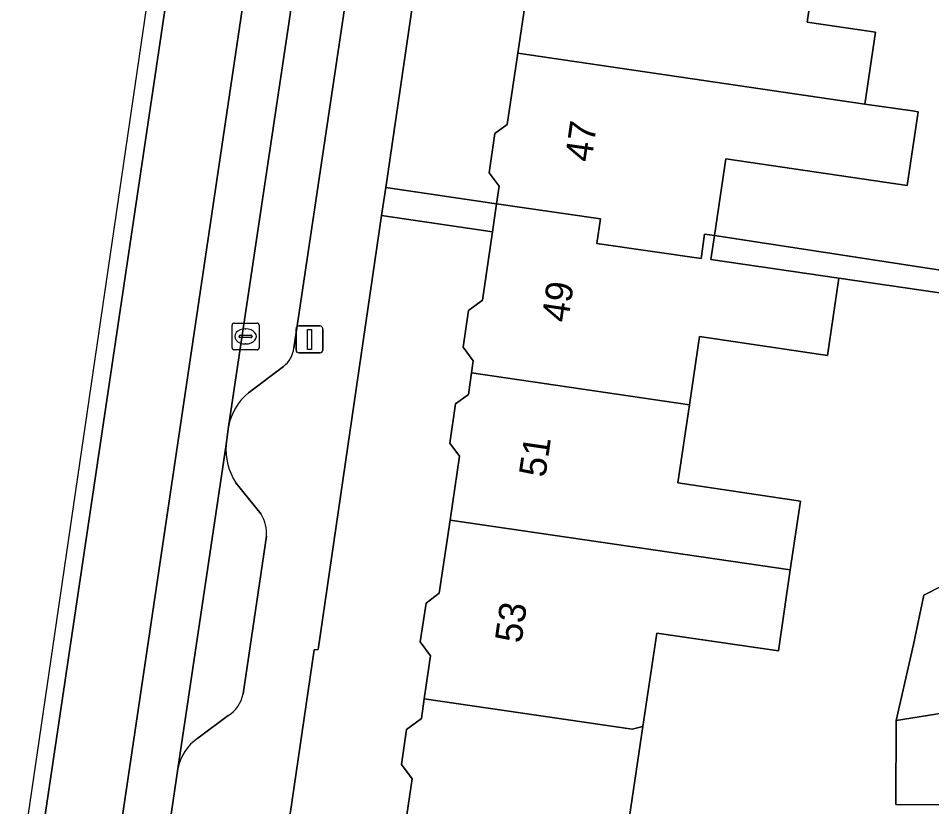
# Model space of a CAD drawing. Extents: x 162250 to 162661, y 380743 to 381606.
# Drawn here: x 162321.06 to 162355.04, y 381382.1 to 381411.43 of the extents above; entities that cross this region are included whole.
import ezdxf

# ---------------------------------------------------------------- set-up
doc = ezdxf.new("R2010")
doc.units = 0
for name, color, linetype in [('IMGEO_Erf', 7, 'Continuous'), ('IMGEO_Kolk', 7, 'Continuous'), ('IMGEO_Lichtmast', 7, 'Continuous'), ('IMGEO_Pand', 7, 'Continuous'), ('IMGEO_Pand_nummerreeks', 7, 'Continuous'), ('IMGEO_Parkeervlak_open', 7, 'Continuous'), ('IMGEO_Rijbaan_lokaal_gesloten', 7, 'Continuous'), ('IMGEO_Rijbaan_lokaal_open', 7, 'Continuous'), ('IMGEO_Voetpad_open', 7, 'Continuous')]:
    doc.layers.add(name, color=color, linetype=linetype)

msp = doc.modelspace()

# ---------------------------------------------------------------- linework, layer by layer
at = {"layer": 'IMGEO_Erf'}
for points in [[(162338.89, 381433.553), (162334.728, 381405.133), (162338.853, 381404.529), (162338.949, 381405.179), (162338.573, 381405.685), (162338.788, 381407.138), (162339.25, 381407.481), (162339.641, 381410.127), (162340.001, 381412.566)], [(162350.768, 381413.723), (162350.412, 381411.289), (162352.951, 381410.914), (162352.555, 381408.238), (162354.32, 381407.98), (162354.536, 381407.946), (162354.13, 381405.202), (162347.377, 381406.2), (162346.955, 381403.343), (162373.077, 381399.345), (162375.677, 381398.98), (162378.363, 381398.602), (162381.05, 381398.225), (162383.737, 381397.847), (162386.424, 381397.47), (162386.104, 381406.654), (162398.76, 381412.894)], [(162335.056, 381378.696), (162335.711, 381383.129), (162335.309, 381383.67), (162335.501, 381384.968), (162336.054, 381385.378), (162336.163, 381386.115), (162336.399, 381387.712), (162336.013, 381388.232), (162336.226, 381389.674), (162336.72, 381390.041), (162337.122, 381392.761), (162337.473, 381395.14), (162337.112, 381395.626), (162337.327, 381397.082), (162337.801, 381397.434), (162337.919, 381398.234), (162337.986, 381398.684), (162337.606, 381399.195), (162337.808, 381400.561), (162338.323, 381400.943), (162338.699, 381403.489), (162334.576, 381404.093), (162332.211, 381387.945), (162332.068, 381387.938), (162330.281, 381375.735)], [(162360.858, 381400.414), (162351.59, 381401.756), (162351.165, 381398.884), (162346.399, 381399.588), (162346.024, 381397.048), (162345.595, 381394.143), (162350.157, 381393.469), (162349.779, 381390.908), (162349.334, 381387.89), (162344.808, 381388.559), (162344.295, 381385.086), (162343.8, 381381.738)]]:
    msp.add_lwpolyline(points, dxfattribs=at)
msp.add_lwpolyline([(162358.135, 381391.689), (162356.982, 381385.822), (162356.26, 381382.172), (162353.699, 381382.181), (162353.72, 381385.307), (162354.36, 381388.13), (162354.752, 381389.967)], close=True, dxfattribs=at)
at = {"layer": 'IMGEO_Kolk'}
for p, q in [((162329.012, 381399.166), (162329.012, 381400.018)), ((162329.087, 381400.092), (162329.939, 381400.092)), ((162330.013, 381400.018), (162330.013, 381399.166)), ((162329.5, 381399.872), (162329.525, 381399.872)), ((162329.271, 381399.586), (162329.271, 381399.598)), ((162329.709, 381399.549), (162329.311, 381399.549)), ((162329.314, 381399.635), (162329.712, 381399.635)), ((162329.755, 381399.598), (162329.755, 381399.586)), ((162329.939, 381399.092), (162329.087, 381399.092)), ((162329.523, 381399.312), (162329.498, 381399.312))]:
    msp.add_line(p, q, dxfattribs=at)
for points in [[(162329.012, 381399.166), (162329.012, 381400.018)], [(162329.087, 381400.092), (162329.939, 381400.092)], [(162330.013, 381400.018), (162330.013, 381399.166)], [(162329.939, 381399.092), (162329.087, 381399.092)]]:
    msp.add_lwpolyline(points, dxfattribs=at)
for centre, radius, start, end in [((162329.089, 381400.016), 0.0765, 91.552, 178.448), ((162329.089, 381400.016), 0.0765, 91.552, 178.448), ((162329.937, 381400.016), 0.0765, 1.552, 88.448), ((162329.937, 381400.016), 0.0765, 1.552, 88.448), ((162329.311, 381399.595), 0.0403, 85.8775, 175.7526), ((162329.308, 381399.585), 0.0366, 178.938, 274.7102), ((162329.712, 381399.592), 0.043, 264.8664, 352.4533), ((162329.716, 381399.597), 0.0386, 1.7309, 96.639), ((162329.089, 381399.168), 0.0765, 181.552, 268.448), ((162329.089, 381399.168), 0.0765, 181.552, 268.448), ((162329.937, 381399.168), 0.0765, 271.552, 358.448), ((162329.937, 381399.168), 0.0765, 271.552, 358.448)]:
    msp.add_arc(centre, radius, start, end, dxfattribs=at)
for centre, major_axis, ratio, start_param, end_param in [((162329.499, 381399.592), (-0.387, 0.002), 0.722429, 4.712389, 7.853982), ((162329.524, 381399.592), (-0.39, 0.002), 0.717154, 1.570796, 4.712389)]:
    msp.add_ellipse(centre, major_axis=major_axis, ratio=ratio, start_param=start_param, end_param=end_param, dxfattribs=at)
at = {"layer": 'IMGEO_Lichtmast'}
for p, q in [((162331.393, 381399.081), (162331.393, 381399.881)), ((162331.393, 381399.881), (162331.393, 381399.081)), ((162331.493, 381399.981), (162332.283, 381399.981)), ((162332.283, 381399.981), (162331.493, 381399.981)), ((162332.383, 381399.881), (162332.383, 381399.081)), ((162332.383, 381399.081), (162332.383, 381399.881)), ((162332.283, 381398.981), (162331.493, 381398.981)), ((162331.493, 381398.981), (162332.283, 381398.981))]:
    msp.add_line(p, q, dxfattribs=at)
msp.add_lwpolyline([(162331.813, 381399.856), (162331.963, 381399.856), (162331.963, 381399.106), (162331.813, 381399.106), (162331.813, 381399.856)], dxfattribs=at)
for centre, start, end in [((162331.493, 381399.881), 90, 180), ((162331.493, 381399.881), 90, 180), ((162332.283, 381399.881), 0, 90), ((162332.283, 381399.881), 360, 90), ((162331.493, 381399.081), 180, 270), ((162331.493, 381399.081), 180, 270), ((162332.283, 381399.081), 270, 0), ((162332.283, 381399.081), 270, 0)]:
    msp.add_arc(centre, 0.1, start, end, dxfattribs=at)
at = {"layer": 'IMGEO_Pand'}
for points in [[(162350.768, 381413.723), (162350.805, 381413.95), (162348.599, 381414.289), (162348.734, 381415.534), (162340.6, 381416.724), (162340.321, 381414.841), (162339.852, 381414.492), (162339.639, 381413.054), (162340.001, 381412.566), (162339.641, 381410.127), (162352.555, 381408.238), (162352.951, 381410.914), (162350.412, 381411.289)], [(162347.377, 381406.2), (162354.13, 381405.202), (162354.536, 381407.946), (162354.32, 381407.98), (162352.555, 381408.238), (162339.641, 381410.127), (162339.25, 381407.481), (162338.788, 381407.138), (162338.573, 381405.685), (162338.949, 381405.179), (162338.853, 381404.529), (162342.712, 381403.964), (162342.579, 381403.056), (162346.457, 381402.489), (162346.59, 381403.397), (162346.955, 381403.343)], [(162351.59, 381401.756), (162346.825, 381402.46), (162346.955, 381403.343), (162346.59, 381403.397), (162346.457, 381402.489), (162342.579, 381403.056), (162342.712, 381403.964), (162338.853, 381404.529), (162338.699, 381403.489), (162338.323, 381400.943), (162337.808, 381400.561), (162337.606, 381399.195), (162337.986, 381398.684), (162337.919, 381398.234), (162346.024, 381397.048), (162346.399, 381399.588), (162351.165, 381398.884)], [(162346.024, 381397.048), (162337.919, 381398.234), (162337.801, 381397.434), (162337.327, 381397.082), (162337.112, 381395.626), (162337.473, 381395.14), (162337.122, 381392.761), (162349.779, 381390.908), (162350.157, 381393.469), (162345.595, 381394.143)], [(162349.779, 381390.908), (162337.122, 381392.761), (162336.72, 381390.041), (162336.226, 381389.674), (162336.013, 381388.232), (162336.399, 381387.712), (162336.163, 381386.115), (162343.896, 381384.983), (162344.295, 381385.086), (162344.808, 381388.559), (162349.334, 381387.89)], [(162353.72, 381385.307), (162356.982, 381385.822), (162358.135, 381391.689), (162354.752, 381389.967), (162354.36, 381388.13)], [(162344.295, 381385.086), (162343.896, 381384.983), (162336.163, 381386.115), (162336.054, 381385.378), (162335.501, 381384.968), (162335.309, 381383.67), (162335.711, 381383.129), (162335.056, 381378.696), (162336.071, 381377.329), (162344.528, 381376.079), (162344.66, 381376.975), (162348.321, 381376.436), (162348.988, 381380.972), (162343.8, 381381.738)], [(162356.982, 381385.822), (162353.72, 381385.307), (162353.699, 381382.181), (162356.26, 381382.172)]]:
    msp.add_lwpolyline(points, close=True, dxfattribs=at)
at = {"layer": 'IMGEO_Parkeervlak_open'}
for points in [[(162335.68, 381441.768), (162328.878, 381396.23)], [(162331.307, 381399.157), (162336.334, 381432.816)], [(162329.621, 381397.5), (162330.928, 381398.477)], [(162328.79, 381395.572), (162326.988, 381383.502)], [(162330.094, 381392.976), (162329.156, 381394.151)], [(162329.418, 381386.291), (162330.287, 381392.156)], [(162327.738, 381384.647), (162328.862, 381385.485)]]:
    msp.add_lwpolyline(points, dxfattribs=at)
for centre, radius, start, end in [((162330.281, 381399.283), 1.034, 308.7422, 352.9913), ((162331.004, 381395.839), 2.161, 129.7702, 169.5711), ((162330.948, 381395.37), 2.168, 174.6603, 214.2266), ((162329.014, 381392.289), 1.279, 354.0243, 32.4645), ((162328.202, 381386.535), 1.241, 302.1584, 348.6438), ((162328.76, 381383.159), 1.805, 124.489, 169.0597)]:
    msp.add_arc(centre, radius, start, end, dxfattribs=at)
at = {"layer": 'IMGEO_Rijbaan_lokaal_gesloten'}
for points in [[(162321.057, 381379.295), (162321.057, 381379.295), (162321.673, 381379.215), (162345.986, 381542.729), (162344.886, 381542.888), (162337.941, 381494.596)], [(162342.842, 381489.774), (162343.13, 381491.968), (162349.998, 381538.218), (162350.562, 381542.047), (162348.846, 381542.303), (162344.03, 381510.414), (162324.497, 381378.848), (162326.277, 381378.617), (162326.988, 381383.502), (162328.79, 381395.572), (162328.878, 381396.23), (162335.68, 381441.768), (162335.989, 381444.267)]]:
    msp.add_lwpolyline(points, close=True, dxfattribs=at)
at = {"layer": 'IMGEO_Rijbaan_lokaal_open'}
msp.add_lwpolyline([(162321.673, 381379.215), (162324.497, 381378.848), (162344.03, 381510.414), (162348.846, 381542.303), (162345.986, 381542.729)], close=True, dxfattribs=at)
at = {"layer": 'IMGEO_Voetpad_open'}
for points in [[(162331.099, 381370.386), (162331.101, 381374.491), (162330.281, 381375.735), (162332.068, 381387.938), (162332.211, 381387.945), (162334.576, 381404.093), (162334.728, 381405.133), (162338.89, 381433.553), (162339.214, 381435.764), (162339.996, 381441.104), (162343.449, 381463.697), (162345.762, 381479.541), (162345.951, 381480.835), (162350.479, 381511.856), (162350.791, 381513.94), (162350.929, 381514.861), (162358.055, 381562.41), (162359.403, 381573.306), (162359.448, 381578.123), (162362.669, 381579.584), (162363.286, 381580.314), (162361.6, 381584.081), (162363.369, 381585.251), (162370.283, 381588.375)], [(162337.12, 381438.08), (162336.991, 381437.217), (162336.334, 381432.816), (162331.307, 381399.157)], [(162330.928, 381398.477), (162329.621, 381397.5)], [(162328.878, 381396.23), (162328.79, 381395.572)], [(162329.156, 381394.151), (162330.094, 381392.976)], [(162330.287, 381392.156), (162329.418, 381386.291)], [(162328.862, 381385.485), (162327.738, 381384.647)], [(162326.988, 381383.502), (162326.277, 381378.617), (162326.057, 381376.827)]]:
    msp.add_lwpolyline(points, dxfattribs=at)
for points in [[(162338.853, 381404.529), (162334.728, 381405.133), (162334.576, 381404.093), (162338.699, 381403.489)], [(162346.955, 381403.343), (162346.825, 381402.46), (162351.59, 381401.756), (162360.858, 381400.414), (162360.87, 381400.499), (162368.468, 381399.398), (162368.328, 381398.244), (162365.555, 381396.74), (162362.518, 381395.093), (162362.518, 381394.554), (162362.518, 381394.226), (162362.518, 381394.063), (162366.054, 381395.832), (162373.077, 381399.345)]]:
    msp.add_lwpolyline(points, close=True, dxfattribs=at)
for centre, radius, start, end in [((162330.281, 381399.283), 1.034, 308.7422, 352.9913), ((162331.004, 381395.839), 2.161, 129.7702, 169.5711), ((162330.948, 381395.37), 2.168, 174.6603, 214.2266), ((162329.014, 381392.289), 1.279, 354.0243, 32.4645), ((162328.202, 381386.535), 1.241, 302.1584, 348.6438), ((162328.76, 381383.159), 1.805, 124.489, 169.0597)]:
    msp.add_arc(centre, radius, start, end, dxfattribs=at)

# ---------------------------------------------------------------- texts
at = {"layer": 'IMGEO_Pand_nummerreeks'}
for s, rotation, p in [('47', 81.9903, (162342.381, 381406.052)), ('49', 81.5663, (162341.509, 381400.083)), ('51', 81.7095, (162340.663, 381394.318)), ('53', 81.7897, (162339.772, 381388.152))]:
    msp.add_text(s, height=1, rotation=rotation, dxfattribs=at).set_placement(p)

doc.saveas('drawing.dxf')
